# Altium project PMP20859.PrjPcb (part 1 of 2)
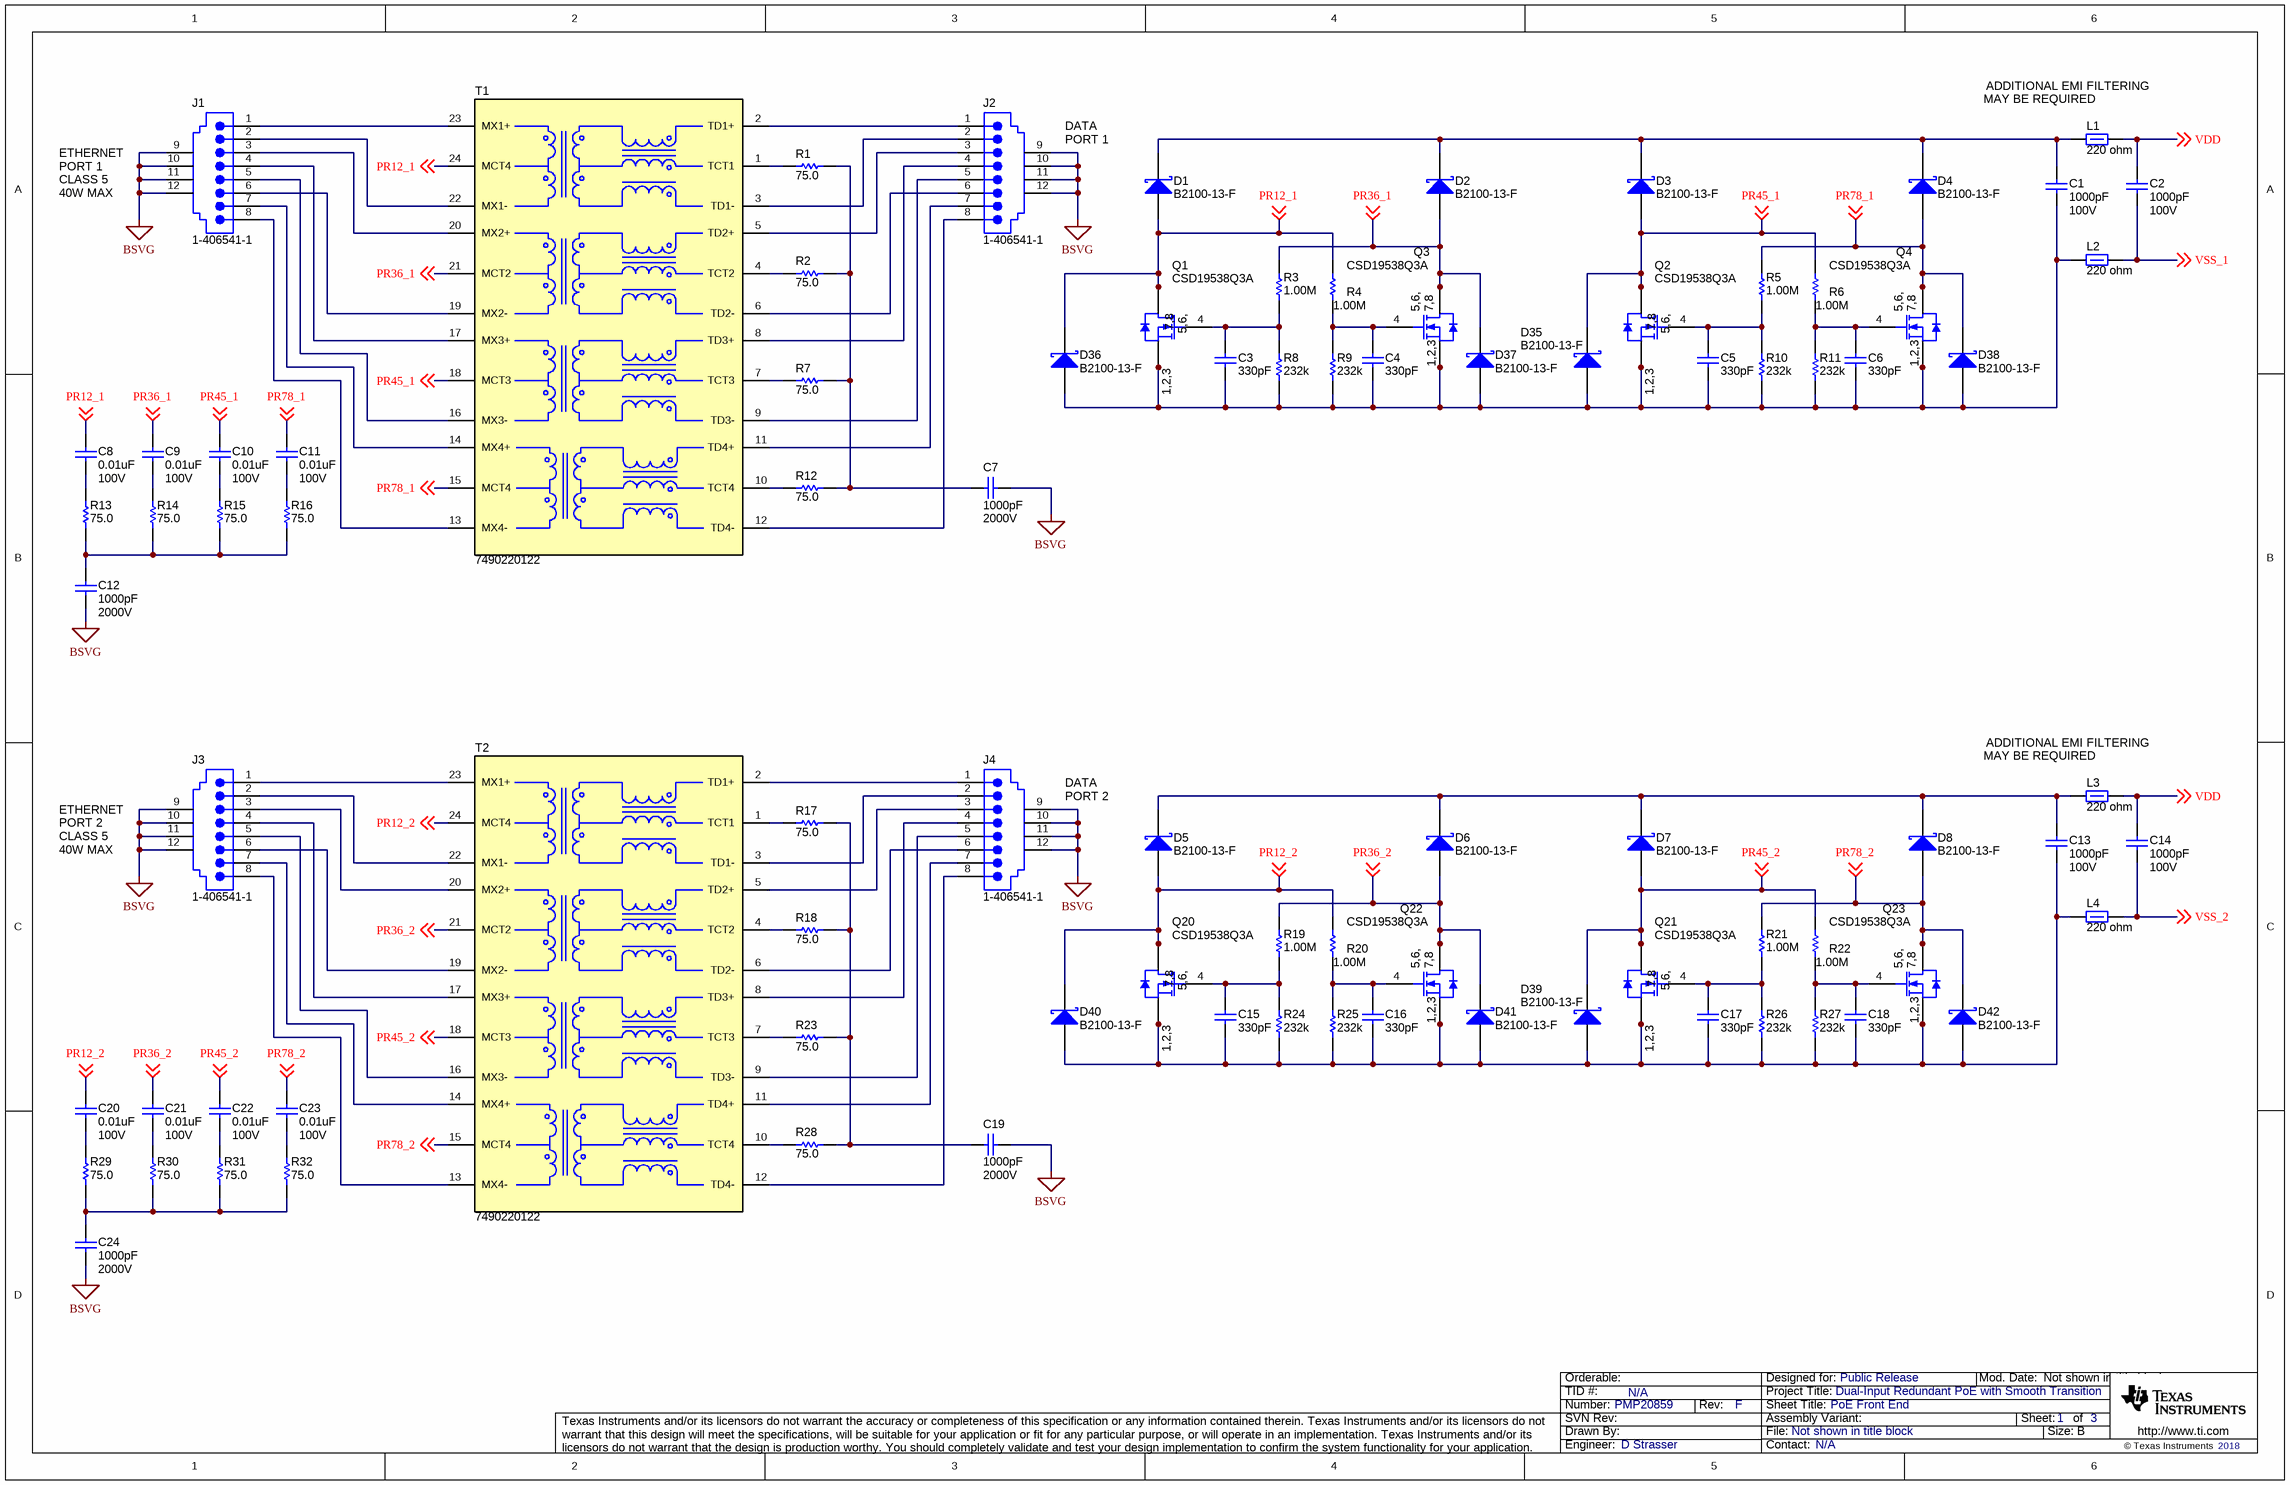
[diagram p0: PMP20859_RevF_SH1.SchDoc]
CopyrightYear: 2018; PCB_Layout: D Strasser; PCB_Rev: F; PRJ_Customer: Public Release; PRJ_Engineer: D Strasser; PRJ_Number: PMP20859; PRJ_Title: Dual-Input Redundant PoE with Smooth Transition; SCH_Rev: F; TechSupport: N/A; TID: N/A
3 sheets, 264 parts. Net scope: global (net labels, ports and power ports of the same name join across sheets).
Board file: PMP20859_RevF.PcbDoc
Sheets:
  PMP20859_RevF_SH1.SchDoc
  PMP20859_RevF_SH2.SchDoc
  PMP20859_RevF_SH3.SchDoc

## Sheet PMP20859_RevF_SH1.SchDoc: PoE Front End
size 431 x 279 mm; Date: Not shown in title block; ApprovedBy: Not shown in title block; CheckedBy: Not shown in title block; Author: Not shown in title block; CompanyName: Not shown in title block; Engineer: Not shown in title block; Organization: Not shown in title block; Address1: Not shown in title block; Address2: Not shown in title block; Address3: Not shown in title block; Address4: Not shown in title block; DocumentNumber: 1; Revision: Use project parameter SCH_Rev; SheetNumber: 1; SheetTotal: 3; PageSetup: Record=PageOptions¦CenterHorizontal=True¦CenterVertical=True¦PrintScale=1.00¦XCorrection=1.00¦YCorrection=1.00¦PrintKind=0¦BorderSize=5000000¦LeftOffset=0¦BottomOffset=0¦Orientation=2¦PaperLength=1000¦PaperWidth=1000¦Scale=100¦PaperSource=15¦PrintQuality=600¦MediaType=1¦DitherType=10¦PaperKind=Letter¦PrintScaleMode=1

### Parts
C1  ValueDisplayed: 1000pF  Value2: 100V  [0603_HV]  (hidden comment: Capacitor)
C2  ValueDisplayed: 1000pF  Value2: 100V  [0603_HV]  (hidden comment: Capacitor)
C3  ValueDisplayed: 330pF  [0603L]  (hidden comment: Capacitor)
C4  ValueDisplayed: 330pF  [0603L]  (hidden comment: Capacitor)
C5  ValueDisplayed: 330pF  [0603L]  (hidden comment: Capacitor)
C6  ValueDisplayed: 330pF  [0603L]  (hidden comment: Capacitor)
C7  ValueDisplayed: 1000pF  Value2: 2000V  [1812]  (hidden comment: Capacitor)
C8  ValueDisplayed: 0.01uF  Value2: 100V  [0603L]  (hidden comment: Capacitor)
C9  ValueDisplayed: 0.01uF  Value2: 100V  [0603L]  (hidden comment: Capacitor)
C10  ValueDisplayed: 0.01uF  Value2: 100V  [0603L]  (hidden comment: Capacitor)
C11  ValueDisplayed: 0.01uF  Value2: 100V  [0603L]  (hidden comment: Capacitor)
C12  ValueDisplayed: 1000pF  Value2: 2000V  [1812]  (hidden comment: Capacitor)
C13  ValueDisplayed: 1000pF  Value2: 100V  [0603_HV]  (hidden comment: Capacitor)
C14  ValueDisplayed: 1000pF  Value2: 100V  [0603_HV]  (hidden comment: Capacitor)
C15  ValueDisplayed: 330pF  [0603L]  (hidden comment: Capacitor)
C16  ValueDisplayed: 330pF  [0603L]  (hidden comment: Capacitor)
C17  ValueDisplayed: 330pF  [0603L]  (hidden comment: Capacitor)
C18  ValueDisplayed: 330pF  [0603L]  (hidden comment: Capacitor)
C19  ValueDisplayed: 1000pF  Value2: 2000V  [1812]  (hidden comment: Capacitor)
C20  ValueDisplayed: 0.01uF  Value2: 100V  [0603L]  (hidden comment: Capacitor)
C21  ValueDisplayed: 0.01uF  Value2: 100V  [0603L]  (hidden comment: Capacitor)
C22  ValueDisplayed: 0.01uF  Value2: 100V  [0603L]  (hidden comment: Capacitor)
C23  ValueDisplayed: 0.01uF  Value2: 100V  [0603L]  (hidden comment: Capacitor)
C24  ValueDisplayed: 1000pF  Value2: 2000V  [1812]  (hidden comment: Capacitor)
D1  B2100-13-F  [SMB]
D2  B2100-13-F  [SMB]
D3  B2100-13-F  [SMB]
D4  B2100-13-F  [SMB]
D5  B2100-13-F  [SMB]
D6  B2100-13-F  [SMB]
D7  B2100-13-F  [SMB]
D8  B2100-13-F  [SMB]
D35  B2100-13-F  [SMB]
D36  B2100-13-F  [SMB]
D37  B2100-13-F  [SMB]
D38  B2100-13-F  [SMB]
D39  B2100-13-F  [SMB]
D40  B2100-13-F  [SMB]
D41  B2100-13-F  [SMB]
D42  B2100-13-F  [SMB]
J1  1-406541-1  [TEC_1-406541-1]
J2  1-406541-1  [TEC_1-406541-1]
J3  1-406541-1  [TEC_1-406541-1]
J4  1-406541-1  [TEC_1-406541-1]
L1  value 220 ohm  [0603]  (hidden comment: Ferrite_Bead)
L2  value 220 ohm  [0603]  (hidden comment: Ferrite_Bead)
L3  value 220 ohm  [0603]  (hidden comment: Ferrite_Bead)
L4  value 220 ohm  [0603]  (hidden comment: Ferrite_Bead)
Q1  CSD19538Q3A  [DNH0008A_NV]
Q2  CSD19538Q3A  [DNH0008A_NV]
Q3  CSD19538Q3A  [DNH0008A_NV]
Q4  CSD19538Q3A  [DNH0008A_NV]
Q20  CSD19538Q3A  [DNH0008A_NV]
Q21  CSD19538Q3A  [DNH0008A_NV]
Q22  CSD19538Q3A  [DNH0008A_NV]
Q23  CSD19538Q3A  [DNH0008A_NV]
R1  value 75.0  [0603L]  (hidden comment: Resistor)
R2  value 75.0  [0603L]  (hidden comment: Resistor)
R3  ValueDisplayed: 1.00M  [0603L]  (hidden comment: Resistor)
R4  ValueDisplayed: 1.00M  [0603L]  (hidden comment: Resistor)
R5  ValueDisplayed: 1.00M  [0603L]  (hidden comment: Resistor)
R6  ValueDisplayed: 1.00M  [0603L]  (hidden comment: Resistor)
R7  value 75.0  [0603L]  (hidden comment: Resistor)
R8  ValueDisplayed: 232k  [0603L]  (hidden comment: Resistor)
R9  ValueDisplayed: 232k  [0603L]  (hidden comment: Resistor)
R10  ValueDisplayed: 232k  [0603L]  (hidden comment: Resistor)
R11  ValueDisplayed: 232k  [0603L]  (hidden comment: Resistor)
R12  value 75.0  [0603L]  (hidden comment: Resistor)
R13  value 75.0  [0603L]  (hidden comment: Resistor)
R14  value 75.0  [0603L]  (hidden comment: Resistor)
R15  value 75.0  [0603L]  (hidden comment: Resistor)
R16  value 75.0  [0603L]  (hidden comment: Resistor)
R17  value 75.0  [0603L]  (hidden comment: Resistor)
R18  value 75.0  [0603L]  (hidden comment: Resistor)
R19  ValueDisplayed: 1.00M  [0603L]  (hidden comment: Resistor)
R20  ValueDisplayed: 1.00M  [0603L]  (hidden comment: Resistor)
R21  ValueDisplayed: 1.00M  [0603L]  (hidden comment: Resistor)
R22  ValueDisplayed: 1.00M  [0603L]  (hidden comment: Resistor)
R23  value 75.0  [0603L]  (hidden comment: Resistor)
R24  ValueDisplayed: 232k  [0603L]  (hidden comment: Resistor)
R25  ValueDisplayed: 232k  [0603L]  (hidden comment: Resistor)
R26  ValueDisplayed: 232k  [0603L]  (hidden comment: Resistor)
R27  ValueDisplayed: 232k  [0603L]  (hidden comment: Resistor)
R28  value 75.0  [0603L]  (hidden comment: Resistor)
R29  value 75.0  [0603L]  (hidden comment: Resistor)
R30  value 75.0  [0603L]  (hidden comment: Resistor)
R31  value 75.0  [0603L]  (hidden comment: Resistor)
R32  value 75.0  [0603L]  (hidden comment: Resistor)
T1  7490220122  [Wurth_7490220122]
T2  7490220122  [Wurth_7490220122]

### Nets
BSVG: C7.1 C12.2 C19.1 C24.2 J1.9 J1.10 J1.11 J1.12 J2.9 J2.10 J2.11 J2.12 J3.9 J3.10 J3.11 J3.12 J4.9 J4.10 J4.11 J4.12
PR12_1: C8.1 D1.2(A) D36.1(K) Q1.5(D) Q1.6(D) Q1.7(D) Q1.8(D) Q1.9(D) R4.1 T1.24(MCT4) ; off-sheet PR12_1
PR12_2: C20.1 D5.2(A) D40.1(K) Q20.5(D) Q20.6(D) Q20.7(D) Q20.8(D) Q20.9(D) R20.1 T2.24(MCT4) ; off-sheet PR12_2
PR36_1: C9.1 D2.2(A) D37.1(K) Q3.5(D) Q3.6(D) Q3.7(D) Q3.8(D) Q3.9(D) R3.1 T1.21(MCT2) ; off-sheet PR36_1
PR36_2: C21.1 D6.2(A) D41.1(K) Q22.5(D) Q22.6(D) Q22.7(D) Q22.8(D) Q22.9(D) R19.1 T2.21(MCT2) ; off-sheet PR36_2
PR45_1: C10.1 D3.2(A) D35.1(K) Q2.5(D) Q2.6(D) Q2.7(D) Q2.8(D) Q2.9(D) R6.1 T1.18(MCT3) ; off-sheet PR45_1
PR45_2: C22.1 D7.2(A) D39.1(K) Q21.5(D) Q21.6(D) Q21.7(D) Q21.8(D) Q21.9(D) R22.1 T2.18(MCT3) ; off-sheet PR45_2
PR78_1: C11.1 D4.2(A) D38.1(K) Q4.5(D) Q4.6(D) Q4.7(D) Q4.8(D) Q4.9(D) R5.1 T1.15(MCT4) ; off-sheet PR78_1
PR78_2: C23.1 D8.2(A) D42.1(K) Q23.5(D) Q23.6(D) Q23.7(D) Q23.8(D) Q23.9(D) R21.1 T2.15(MCT4) ; off-sheet PR78_2
VDD: C2.1 C14.1 L1.2 L3.2 ; off-sheet VDD
VSS_1: C2.2 L2.2 ; off-sheet VSS_1
VSS_2: C14.2 L4.2 ; off-sheet VSS_2
NetC1_1: C1.1 D1.1(K) D2.1(K) D3.1(K) D4.1(K) L1.1
NetC1_2: C1.2 C3.2 C4.2 C5.2 C6.2 D35.2(A) D36.2(A) D37.2(A) D38.2(A) L2.1 Q1.1(S) Q1.2(S) Q1.3(S) Q2.1(S) Q2.2(S) Q2.3(S) Q3.1(S) Q3.2(S) Q3.3(S) Q4.1(S) Q4.2(S) Q4.3(S) R8.1 R9.1 R10.1 R11.1
NetC3_1: C3.1 Q1.4(G) R3.2 R8.2
NetC4_1: C4.1 Q3.4(G) R4.2 R9.2
NetC5_1: C5.1 Q2.4(G) R5.2 R10.2
NetC6_1: C6.1 Q4.4(G) R6.2 R11.2
NetC7_2: C7.2 R1.1 R2.1 R7.1 R12.1
NetC8_2: C8.2 R13.2
NetC9_2: C9.2 R14.2
NetC10_2: C10.2 R15.2
NetC11_2: C11.2 R16.2
NetC12_1: C12.1 R13.1 R14.1 R15.1 R16.1
NetC13_1: C13.1 D5.1(K) D6.1(K) D7.1(K) D8.1(K) L3.1
NetC13_2: C13.2 C15.2 C16.2 C17.2 C18.2 D39.2(A) D40.2(A) D41.2(A) D42.2(A) L4.1 Q20.1(S) Q20.2(S) Q20.3(S) Q21.1(S) Q21.2(S) Q21.3(S) Q22.1(S) Q22.2(S) Q22.3(S) Q23.1(S) Q23.2(S) Q23.3(S) R24.1 R25.1 R26.1 R27.1
NetC15_1: C15.1 Q20.4(G) R19.2 R24.2
NetC16_1: C16.1 Q22.4(G) R20.2 R25.2
NetC17_1: C17.1 Q21.4(G) R21.2 R26.2
NetC18_1: C18.1 Q23.4(G) R22.2 R27.2
NetC19_2: C19.2 R17.1 R18.1 R23.1 R28.1
NetC20_2: C20.2 R29.2
NetC21_2: C21.2 R30.2
NetC22_2: C22.2 R31.2
NetC23_2: C23.2 R32.2
NetC24_1: C24.1 R29.1 R30.1 R31.1 R32.1
NetJ1_1: J1.1 T1.23(MX1+)
NetJ1_2: J1.2 T1.22(MX1-)
NetJ1_3: J1.3 T1.20(MX2+)
NetJ1_4: J1.4 T1.17(MX3+)
NetJ1_5: J1.5 T1.16(MX3-)
NetJ1_6: J1.6 T1.19(MX2-)
NetJ1_7: J1.7 T1.14(MX4+)
NetJ1_8: J1.8 T1.13(MX4-)
NetJ2_1: J2.1 T1.2(TD1+)
NetJ2_2: J2.2 T1.3(TD1-)
NetJ2_3: J2.3 T1.5(TD2+)
NetJ2_4: J2.4 T1.8(TD3+)
NetJ2_5: J2.5 T1.9(TD3-)
NetJ2_6: J2.6 T1.6(TD2-)
NetJ2_7: J2.7 T1.11(TD4+)
NetJ2_8: J2.8 T1.12(TD4-)
NetJ3_1: J3.1 T2.23(MX1+)
NetJ3_2: J3.2 T2.22(MX1-)
NetJ3_3: J3.3 T2.20(MX2+)
NetJ3_4: J3.4 T2.17(MX3+)
NetJ3_5: J3.5 T2.16(MX3-)
NetJ3_6: J3.6 T2.19(MX2-)
NetJ3_7: J3.7 T2.14(MX4+)
NetJ3_8: J3.8 T2.13(MX4-)
NetJ4_1: J4.1 T2.2(TD1+)
NetJ4_2: J4.2 T2.3(TD1-)
NetJ4_3: J4.3 T2.5(TD2+)
NetJ4_4: J4.4 T2.8(TD3+)
NetJ4_5: J4.5 T2.9(TD3-)
NetJ4_6: J4.6 T2.6(TD2-)
NetJ4_7: J4.7 T2.11(TD4+)
NetJ4_8: J4.8 T2.12(TD4-)
NetR1_2: R1.2 T1.1(TCT1)
NetR2_2: R2.2 T1.4(TCT2)
NetR7_2: R7.2 T1.7(TCT3)
NetR12_2: R12.2 T1.10(TCT4)
NetR17_2: R17.2 T2.1(TCT1)
NetR18_2: R18.2 T2.4(TCT2)
NetR23_2: R23.2 T2.7(TCT3)
NetR28_2: R28.2 T2.10(TCT4)

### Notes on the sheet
- (near L1) MAY BE REQUIRED
- (near L1) ADDITIONAL EMI FILTERING
- ETHERNET
- PORT 1
- (near J2) DATA
- (near J2) PORT 1
- 40W MAX
- CLASS 5
- (near L3) MAY BE REQUIRED
- (near L3) ADDITIONAL EMI FILTERING
- PORT 2
- (near J4) DATA
- (near J4) PORT 2

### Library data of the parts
C1 C2 C13 C14 = CMP-0007053-4: CAP, CERM, 1000 pF, 100 V, +/- 10%, X7R, 0603; PartNumber: C1608X7R2A102K080AA; Manufacturer: TDK; Polarized: N; Value: 1000pF; U/M: EA; Cap_F: 1nF; Value1: Unknown; TaMin_C: -55°C; TaMax_C: 125°C; Cap_Case: 0603; SizeArea_mm2: 1.28; SizeAreaWB_mm2: 4.68; SizeX_mm: 1.6; SizeY_mm: 0.8; SizeZ_mm: 1; AEC Category: Q200
C3-C6 C15-C18 = CMP-0007209-4: CAP, CERM, 330 pF, 50 V, +/- 5%, C0G/NP0, 0603; PartNumber: GRM1885C1H331JA01D; Manufacturer: MuRata; Polarized: N; Value: 330pF; U/M: EA; Value1: Unknown; VDC_V: 50V; TaMin_C: -55°C; TaMax_C: 125°C; Cap_Case: 0603; SizeArea_mm2: 1.28; SizeAreaWB_mm2: 4.68; SizeX_mm: 1.6; SizeY_mm: 0.8; SizeZ_mm: 1; AEC Category: Q200
C7 C12 C19 C24 = CMP-0009438-2: CAP, CERM, 1000 pF, 2000 V, +/- 10%, X7R, 1812; PartNumber: GR443QR73D102KW01L; Manufacturer: MuRata; Polarized: N; Value: 1000pF; U/M: EA; Cap_F: 1nF; Value1: Unknown; VDC_V: 2kV; TaMin_C: -55°C; TaMax_C: 125°C; SizeArea_mm2: 14.4; SizeAreaWB_mm2: 23.1; SizeX_mm: 4.5; SizeY_mm: 3.2; SizeZ_mm: 1.35; AEC Category: Q200
C8-C11 C20-C23 = CMP-0007468-5: CAP, CERM, 0.01 uF, 100 V, +/- 10%, X7R, 0603; PartNumber: GRM188R72A103KA01D; Manufacturer: MuRata; Polarized: N; Value: 0.01uF; U/M: EA; Cap_F: 10nF; Value1: Unknown; TaMin_C: -55°C; TaMax_C: 125°C; Cap_Case: 0603; SizeArea_mm2: 1.28; SizeAreaWB_mm2: 4.68; SizeX_mm: 1.6; SizeY_mm: 0.8; SizeZ_mm: 1; AEC Category: Q200
D1-D8 D35-D42 = CMP-0028397-1: Diode, Schottky, 100 V, 2 A, SMB; Manufacturer: Diodes Inc.; Value: 100V; U/M: EA; Vf_V: 7.9dV; Value1: 2A; Value2: 0.79V; TJmax_C: 150°C; RJC_CperW: 15; AEC Category: Q101; Green_Lifecycle: Active; Green_REACh: Passed; SizeArea_mm2: 21.336; SizeAreaWB_mm2: 44.156; SizeX_mm: 5.6; SizeY_mm: 3.81; SizeZ_mm: 2.6
J1-J4 = CMP-0054918-1: RJ45, No LED, tab up, R/A, TH; Manufacturer: TE Connectivity; CNHeader: FALSE; ContactFinish: Gold; CT: TRUE; Green_Lifecycle: Active; Green_REACh: Passed
L1-L4 = CMP-0003425-2: Ferrite Bead, 220 ohm @ 100 MHz, 2.2 A, 0603; PartNumber: MPZ1608S221A; Manufacturer: TDK; Imax_A: 2.2A; DCR_ohm: 0.05; Value1: 0.05 ohm; ZTyp@100MHz_Ohm: 220; SizeArea_mm2: 1.28; SizeAreaWB_mm2: 4.68; SizeX_mm: 1.6; SizeY_mm: 0.8; SizeZ_mm: 1
Q1-Q4 Q20-Q23 = CMP-0000969-2: MOSFET, N-CH, 100 V, 5 A, DNH0008A (VSONP-8); Manufacturer: Texas Instruments; Alternate Manufacturer: None; U/M: EA; ChType: N; Value: 100V; Value2: 7.2 nC; QgTyp_nC: 7.2; Vgs_V: 20V; IdsMax_A: 5A; SizeAreaWB_mm2: 18.49; SizeArea_mm2: 10.89; SizeX_mm: 3.3; SizeZ_mm: 0.9; AEC Category: Q101
R1 R2 R7 R12-R18 R23 R28-R32 = CMP-0022590-4: RES, 75.0, 1%, 0.1 W, AEC-Q200 Grade 0, 0603; PartNumber: CRCW060375R0FKEA; Manufacturer: Vishay-Dale; Res_ohm: 75; Value_Code: 75R0; Power_W: 100mW; Value2: 0.1W; VDC_V: 75V; TempCo: 100 ppm/C; EIA_Code: E96; AEC Category: Q200; AEC Grade: 0; AEC Qualified: Y; SizeArea_mm2: 1.28; SizeX_mm: 1.6; SizeY_mm: 0.8; SizeZ_mm: 1
R3-R6 R19-R22 = CMP-0022138-4: RES, 1.00 M, 1%, 0.1 W, AEC-Q200 Grade 0, 0603; PartNumber: CRCW06031M00FKEA; Manufacturer: Vishay-Dale; Value: 1.00Meg; Res_ohm: 1M; Value_Code: 1M00; Power_W: 100mW; Value2: 0.1W; VDC_V: 75V; TempCo: 100 ppm/C; EIA_Code: E96; SizeArea_mm2: 1.28; SizeX_mm: 1.6; SizeY_mm: 0.8; SizeZ_mm: 1; AEC Category: Q200; AEC Qualified: Y; AEC Grade: 0
R8-R11 R24-R27 = CMP-0022224-4: RES, 232 k, 1%, 0.1 W, AEC-Q200 Grade 0, 0603; PartNumber: CRCW0603232KFKEA; Manufacturer: Vishay-Dale; Value: 232k; Power_W: 100mW; Value2: 0.1W; VDC_V: 75V; TempCo: 100 ppm/C; EIA_Code: E96; SizeArea_mm2: 1.28; SizeX_mm: 1.6; SizeY_mm: 0.8; SizeZ_mm: 1; AEC Category: Q200; AEC Qualified: Y; AEC Grade: 0
T1 T2 = CMP-0030597-1: Transformer, 350 uH, SMT; Manufacturer: Wurth Elektronik; Value: 350uH; Lp: 350; Ind_H: 350µH

## Sheet PMP20859_RevF_SH2.SchDoc: PoE PD's and Seamless Switching
size 431 x 279 mm; Date: Not shown in title block; ApprovedBy: Not shown in title block; CheckedBy: Not shown in title block; Author: Not shown in title block; CompanyName: Not shown in title block; Engineer: Not shown in title block; Organization: Not shown in title block; Address1: Not shown in title block; Address2: Not shown in title block; Address3: Not shown in title block; Address4: Not shown in title block; DocumentNumber: 2; Revision: Use project parameter SCH_Rev; SheetNumber: 2; SheetTotal: 3; PageSetup: Record=PageOptions¦CenterHorizontal=True¦CenterVertical=True¦PrintScale=1.00¦XCorrection=1.00¦YCorrection=1.00¦PrintKind=0¦BorderSize=5000000¦LeftOffset=0¦BottomOffset=0¦Orientation=2¦PaperLength=1000¦PaperWidth=1000¦Scale=100¦PaperSource=15¦PrintQuality=600¦MediaType=1¦DitherType=10¦PaperKind=Letter¦PrintScaleMode=1
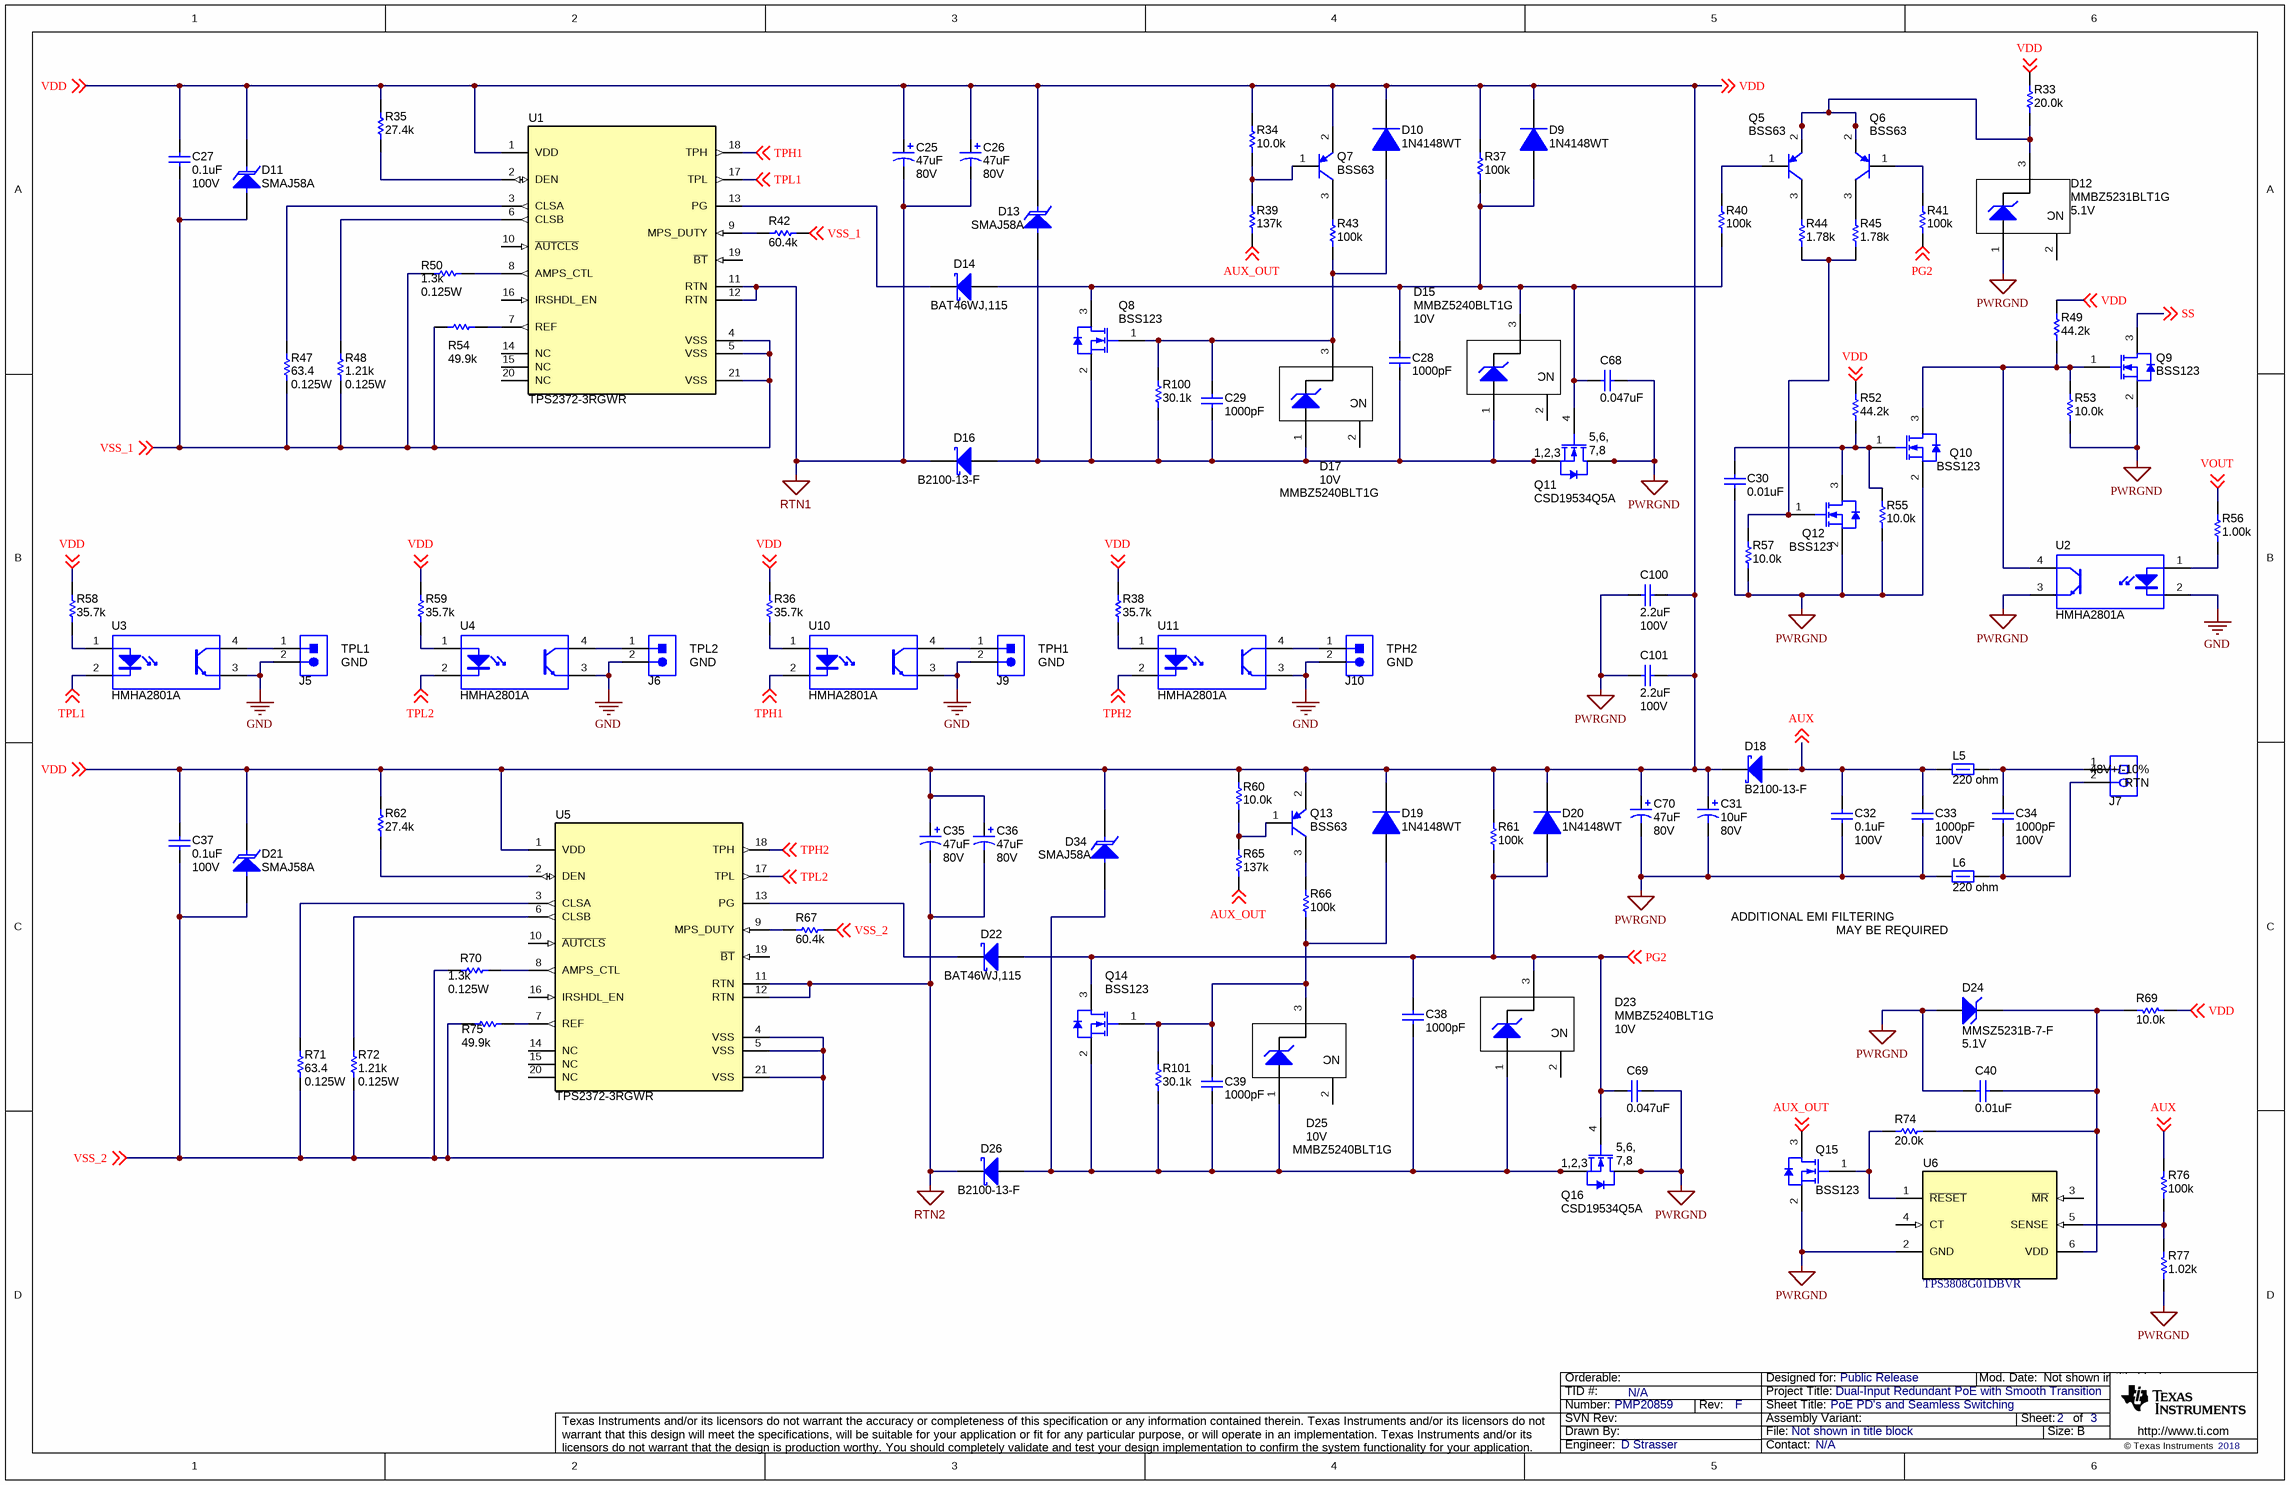
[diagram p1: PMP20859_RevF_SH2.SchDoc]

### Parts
C25  ValueDisplayed: 47uF  Value2: 80V  [SM_RADIAL_G]  (hidden comment: Cap_Polarized)
C26  ValueDisplayed: 47uF  Value2: 80V  [SM_RADIAL_G]  (hidden comment: Cap_Polarized)
C27  ValueDisplayed: 0.1uF  Value2: 100V  [0805_HV]  (hidden comment: Capacitor)
C28  ValueDisplayed: 1000pF  [0603]  (hidden comment: Capacitor)
C29  ValueDisplayed: 1000pF  [0603]  (hidden comment: Capacitor)
C30  ValueDisplayed: 0.01uF  [0603L]  (hidden comment: Capacitor)
C31  ValueDisplayed: 10uF  Value2: 80V  [SM_RADIAL_E]  (hidden comment: Cap_Polarized)
C32  ValueDisplayed: 0.1uF  Value2: 100V  [0805_HV]  (hidden comment: Capacitor)
C33  ValueDisplayed: 1000pF  Value2: 100V  [0603_HV]  (hidden comment: Capacitor)
C34  ValueDisplayed: 1000pF  Value2: 100V  [0603_HV]  (hidden comment: Capacitor)
C35  ValueDisplayed: 47uF  Value2: 80V  [SM_RADIAL_G]  (hidden comment: Cap_Polarized)
C36  ValueDisplayed: 47uF  Value2: 80V  [SM_RADIAL_G]  (hidden comment: Cap_Polarized)
C37  ValueDisplayed: 0.1uF  Value2: 100V  [0805_HV]  (hidden comment: Capacitor)
C38  ValueDisplayed: 1000pF  [0603]  (hidden comment: Capacitor)
C39  ValueDisplayed: 1000pF  [0603]  (hidden comment: Capacitor)
C40  ValueDisplayed: 0.01uF  [0603L]  (hidden comment: Capacitor)
C68  ValueDisplayed: 0.047uF  [0805_HV]  (hidden comment: Capacitor)
C69  ValueDisplayed: 0.047uF  [0805_HV]  (hidden comment: Capacitor)
C70  ValueDisplayed: 47uF  Value2: 80V  [SM_RADIAL_G]  (hidden comment: Cap_Polarized)
C100  ValueDisplayed: 2.2uF  Value2: 100V  [1210_270]  (hidden comment: Capacitor)
C101  ValueDisplayed: 2.2uF  Value2: 100V  [1210_270]  (hidden comment: Capacitor)
D9  1N4148WT  [Fairchild_SOD-523F]
D10  1N4148WT  [Fairchild_SOD-523F]
D11  SMAJ58A  [SMA]
D12  MMBZ5231BLT1G  value 5.1V  [SOT-23]
D13  SMAJ58A  [SMA]
D14  BAT46WJ,115  [SOD-323F]
D15  MMBZ5240BLT1G  value 10V  [SOT-23]
D16  B2100-13-F  [SMB]
D17  MMBZ5240BLT1G  value 10V  [SOT-23]
D18  B2100-13-F  [SMB]
D19  1N4148WT  [Fairchild_SOD-523F]
D20  1N4148WT  [Fairchild_SOD-523F]
D21  SMAJ58A  [SMA]
D22  BAT46WJ,115  [SOD-323F]
D23  MMBZ5240BLT1G  value 10V  [SOT-23]
D24  MMSZ5231B-7-F  value 5.1V  [SOD-123]
D25  MMBZ5240BLT1G  value 10V  [SOT-23]
D26  B2100-13-F  [SMB]
D34  SMAJ58A  [SMA]
J5  PEC02SAAN  [CONN_PEC02SAAN]  (value not drawn)
J6  PEC02SAAN  [CONN_PEC02SAAN]  (value not drawn)
J7  ED555/2DS  [TERM_BLK_ED555-2DS]  (value not drawn)
J9  PEC02SAAN  [CONN_PEC02SAAN]  (value not drawn)
J10  PEC02SAAN  [CONN_PEC02SAAN]  (value not drawn)
L5  value 220 ohm  [0603]  (hidden comment: Ferrite_Bead)
L6  value 220 ohm  [0603]  (hidden comment: Ferrite_Bead)
Q5  BSS63  [SOT-23]
Q6  BSS63  [SOT-23]
Q7  BSS63  [SOT-23]
Q8  BSS123  [SOT-23]
Q9  BSS123  [SOT-23]
Q10  BSS123  [SOT-23]
Q11  CSD19534Q5A  [DQJ0008A]
Q12  BSS123  [SOT-23]
Q13  BSS63  [SOT-23]
Q14  BSS123  [SOT-23]
Q15  BSS123  [SOT-23]
Q16  CSD19534Q5A  [DQJ0008A]
R33  ValueDisplayed: 20.0k  [0603]  (hidden comment: Resistor)
R34  ValueDisplayed: 10.0k  [0603]  (hidden comment: Resistor)
R35  ValueDisplayed: 27.4k  [0603]  (hidden comment: Resistor)
R36  Res_ohm: 35.7k  [0603]  (hidden comment: RC0603FR-0735K7L)
R37  ValueDisplayed: 100k  [0603]  (hidden comment: Resistor)
R38  Res_ohm: 35.7k  [0603]  (hidden comment: RC0603FR-0735K7L)
R39  ValueDisplayed: 137k  [0603]  (hidden comment: Resistor)
R40  ValueDisplayed: 100k  [0603]  (hidden comment: Resistor)
R41  ValueDisplayed: 100k  [0603]  (hidden comment: Resistor)
R42  Res_ohm: 60.4k  [0603]  (hidden comment: CRCW060360K4FKEA)
R43  ValueDisplayed: 100k  [0603]  (hidden comment: Resistor)
R44  ValueDisplayed: 1.78k  [0603]  (hidden comment: Resistor)
R45  ValueDisplayed: 1.78k  [0603]  (hidden comment: Resistor)
R47  ValueDisplayed: 63.4  Value2: 0.125W  [0805_HV]  (hidden comment: Resistor)
R48  ValueDisplayed: 1.21k  Value2: 0.125W  [0805_HV]  (hidden comment: CRCW08051K21FKEA)
R49  ValueDisplayed: 44.2k  [0603L]  (hidden comment: Resistor)
R50  Value2: 0.125W  ValueDisplayed: 1.3k  [0805_HV]  (hidden comment: Resistor)
R52  ValueDisplayed: 44.2k  [0603L]  (hidden comment: Resistor)
R53  ValueDisplayed: 10.0k  [0603L]  (hidden comment: Resistor)
R54  ValueDisplayed: 49.9k  [0603L]  (hidden comment: Resistor)
R55  ValueDisplayed: 10.0k  [0603L]  (hidden comment: Resistor)
R56  ValueDisplayed: 1.00k  [0603L]  (hidden comment: Resistor)
R57  ValueDisplayed: 10.0k  [0603L]  (hidden comment: Resistor)
R58  Res_ohm: 35.7k  [0603]  (hidden comment: RC0603FR-0735K7L)
R59  Res_ohm: 35.7k  [0603]  (hidden comment: RC0603FR-0735K7L)
R60  ValueDisplayed: 10.0k  [0603]  (hidden comment: CRCW060310K0FKEA)
R61  ValueDisplayed: 100k  [0603]  (hidden comment: Resistor)
R62  ValueDisplayed: 27.4k  [0603]  (hidden comment: Resistor)
R65  ValueDisplayed: 137k  [0603]  (hidden comment: Resistor)
R66  ValueDisplayed: 100k  [0603]  (hidden comment: Resistor)
R67  ValueDisplayed: 60.4k  [0603]  (hidden comment: CRCW060360K4FKEA)
R69  ValueDisplayed: 10.0k  [0603L]  (hidden comment: Resistor)
R70  Value2: 0.125W  ValueDisplayed: 1.3k  [0805_HV]  (hidden comment: Resistor)
R71  ValueDisplayed: 63.4  Value2: 0.125W  [0805_HV]  (hidden comment: Resistor)
R72  ValueDisplayed: 1.21k  Value2: 0.125W  [0805_HV]  (hidden comment: CRCW08051K21FKEA)
R74  ValueDisplayed: 20.0k  [0603L]  (hidden comment: Resistor)
R75  ValueDisplayed: 49.9k  [0603L]  (hidden comment: Resistor)
R76  ValueDisplayed: 100k  [0603L]  (hidden comment: Resistor)
R77  ValueDisplayed: 1.02k  [0603]  (hidden comment: Resistor)
R100  ValueDisplayed: 30.1k  [0603]  (hidden comment: Resistor)
R101  ValueDisplayed: 30.1k  [0603]  (hidden comment: Resistor)
U1  TPS2372-3RGWR  [RGW0020B]
U2  HMHA2801A  [MFP04A]
U3  HMHA2801A  [MFP04A]
U4  HMHA2801A  [MFP04A]
U5  TPS2372-3RGWR  [RGW0020B]
U6  TPS3808G01DBVR  [DBV0006A_N]
U10  HMHA2801A  [MFP04A]
U11  HMHA2801A  [MFP04A]

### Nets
GND: J5.2 J6.2 J9.2 J10.2 U2.2(K) U3.3(E) U4.3(E) U10.3(E) U11.3(E)
PWRGND: C30.2 C31.2(-) C32.2 C33.2 C40.1 C68.1 C69.1 C70.2(-) C100.1 C101.1 D12.1(A) D24.2(A) L6.2 Q9.2(S) Q10.2(S) Q11.5(D) Q11.6(D) Q11.7(D) Q11.8(D) Q11.9(D) Q12.2(S) Q15.2(S) Q16.5(D) Q16.6(D) Q16.7(D) Q16.8(D) Q16.9(D) R53.1 R55.1 R57.1 R77.1 U2.3(E) U6.2(GND)
RTN1: C25.2(-) C26.2(-) D16.1(K) U1.11(RTN) U1.12(RTN)
RTN2: C35.2(-) C36.2(-) D26.1(K) U5.11(RTN) U5.12(RTN)
AUX: C32.1 C33.1 D18.2(A) L5.2 R76.2 ; off-sheet AUX
AUX_OUT: Q15.3(D) R39.2 R65.2 ; off-sheet AUX_OUT
PG2: C38.1 C69.2 D20.2(A) D22.2(A) D23.3(K) Q14.3(D) Q16.4(G) R41.1 R61.1 ; off-sheet PG2
SS: Q9.3(D) ; off-sheet SS
TPH1: U1.18(TPH) U10.2(K) ; off-sheet TPH1
TPH2: U5.18(TPH) U11.2(K) ; off-sheet TPH2
TPL1: U1.17(TPL) U3.2(K) ; off-sheet TPL1
TPL2: U4.2(K) U5.17(TPL) ; off-sheet TPL2
VDD: C25.1(+) C26.1(+) C27.2 C31.1(+) C35.1(+) C36.1(+) C37.2 C70.1(+) C100.2 C101.2 D9.1(K) D10.1(K) D11.1(K) D13.1(K) D18.1(K) D19.1(K) D20.1(K) D21.1(K) D34.1(K) Q7.2(E) Q13.2(E) R33.2 R34.2 R35.2 R36.1 R37.2 R38.1 R49.2 R52.1 R58.1 R59.1 R60.2 R61.2 R62.2 R69.2 U1.1(VDD) U5.1(VDD) ; off-sheet VDD
VOUT: R56.2 ; off-sheet VOUT
VSS_1: C27.1 D11.2(A) R42.2 R47.1 R48.1 R50.2 R54.1 U1.4(VSS) U1.5(VSS) U1.21(VSS) ; off-sheet VSS_1
VSS_2: C37.1 D21.2(A) R67.2 R70.2 R71.1 R72.1 R75.1 U5.4(VSS) U5.5(VSS) U5.21(VSS) ; off-sheet VSS_2
NetC28_1: C28.1 C68.2 D9.2(A) D14.2(A) D15.3(K) Q8.3(D) Q11.4(G) R37.1 R40.1
NetC28_2: C28.2 C29.2 D13.2(A) D15.1(A) D16.2(A) D17.1(A) Q8.2(S) Q11.1(S) Q11.2(S) Q11.3(S) R100.1
NetC29_1: C29.1 D10.2(A) D17.3(K) Q8.1(G) R43.1 R100.2
NetC30_1: C30.1 Q10.1(G) Q12.3(D) R52.2 R55.2
NetC34_1: C34.1 J7.1 L5.1
NetC34_2: C34.2 J7.2 L6.1
NetC38_2: C38.2 C39.2 D23.1(A) D25.1(A) D26.2(A) D34.2(A) Q14.2(S) Q16.1(S) Q16.2(S) Q16.3(S) R101.1
NetC39_1: C39.1 D19.2(A) D25.3(K) Q14.1(G) R66.1 R101.2
NetC40_2: C40.2 D24.1(K) R69.1 R74.1 U6.6(VDD)
NetD12_3: D12.3(K) Q5.2(E) Q6.2(E) R33.1
NetD14_1: D14.1(K) U1.13(PG)
NetD22_1: D22.1(K) U5.13(PG)
NetJ5_1: J5.1 U3.4(C)
NetJ6_1: J6.1 U4.4(C)
NetJ9_1: J9.1 U10.4(C)
NetJ10_1: J10.1 U11.4(C)
NetQ5_1: Q5.1(B) R40.2
NetQ5_3: Q5.3(C) R44.1
NetQ6_1: Q6.1(B) R41.2
NetQ6_3: Q6.3(C) R45.2
NetQ7_1: Q7.1(B) R34.1 R39.1
NetQ7_3: Q7.3(C) R43.2
NetQ9_1: Q9.1(G) Q10.3(D) R49.1 R53.2 U2.4(C)
NetQ12_1: Q12.1(G) R44.2 R45.1 R57.2
NetQ13_1: Q13.1(B) R60.1 R65.1
NetQ13_3: Q13.3(C) R66.2
NetQ15_1: Q15.1(G) R74.2 U6.1(~{RESET})
NetR35_1: R35.1 U1.2(DEN)
NetR36_2: R36.2 U10.1(A)
NetR38_2: R38.2 U11.1(A)
NetR42_1: R42.1 U1.9(MPS_DUTY)
NetR47_2: R47.2 U1.3(CLSA)
NetR48_2: R48.2 U1.6(CLSB)
NetR50_1: R50.1 U1.8(AMPS_CTL)
NetR54_2: R54.2 U1.7(REF)
NetR56_1: R56.1 U2.1(A)
NetR58_2: R58.2 U3.1(A)
NetR59_2: R59.2 U4.1(A)
NetR62_1: R62.1 U5.2(DEN)
NetR67_1: R67.1 U5.9(MPS_DUTY)
NetR70_1: R70.1 U5.8(AMPS_CTL)
NetR71_2: R71.2 U5.3(CLSA)
NetR72_2: R72.2 U5.6(CLSB)
NetR75_2: R75.2 U5.7(REF)
NetR76_1: R76.1 R77.2 U6.5(SENSE)

Not connected (* = marked no-connect by the designer): D12 2(NC); D15 2(NC); D17 2(NC); D23 2(NC); D25 2(NC); U1 10(~{AUTCLS}) 14(NC) 15(NC) 16(IRSHDL_EN) 19(~{BT}) 20(NC); U5 10(~{AUTCLS}) 14(NC) 15(NC) 16(IRSHDL_EN) 19(~{BT}) 20(NC); U6 3(~{MR}) 4(CT)

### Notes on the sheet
- TPL1
- (near J5) GND
- TPL2
- (near J6) GND
- TPH1
- (near J9) GND
- (near J10) TPH2
- (near J10) GND
- (near J7) 48V+/-10%
- (near J7) RTN
- (near L6) ADDITIONAL EMI FILTERING
- MAY BE REQUIRED

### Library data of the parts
C25 C26 C35 C36 C70 = CMP-0011200-2: CAP, AL, 47 uF, 80 V, +/- 20%, 0.7 ohm, AEC-Q200 Grade 2, SMD; PartNumber: EEE-FK1K470P; Manufacturer: Panasonic; Polarized: Y; CompType: Capacitor; Value: 47uF; U/M: EA; Cap_F: 47µF; Value1: 0.7 ohm; ESR_ohm: 7d; IRMS_A: 2dA; TaMin_C: -55°C; TaMax_C: 105°C; Cap_Case: G; AEC Category: Q200; AEC Grade: 2; SizeAreaWB_mm2: 172.2; SizeArea_mm2: 123.6; SizeX_mm: 12; SizeY_mm: 10.3; SizeZ_mm: 10.2
C27 C32 C37 = CMP-0007886-2: CAP, CERM, 0.1 uF, 100 V, +/- 10%, X7R, 0805; PartNumber: C2012X7R2A104K125AA; Manufacturer: TDK; Polarized: N; Value: 0.1uF; U/M: EA; Cap_F: 100nF; ESR_ohm: 0.020726; Value1: 0.020726 ohm; IRMS_A: 1.456A; TaMin_C: -55°C; TaMax_C: 125°C; Cap_Case: 0805; SizeArea_mm2: 2.5; SizeAreaWB_mm2: 6.75; SizeX_mm: 2; SizeY_mm: 1.25; SizeZ_mm: 1.45; AEC Category: Q200
C28 C29 C38 C39 = CMP-0007432-5: CAP, CERM, 1000 pF, 50 V, +/- 10%, X7R, 0603; PartNumber: GRM188R71H102KA01D; Manufacturer: MuRata; Polarized: N; Value: 1000pF; U/M: EA; Cap_F: 1nF; Value1: Unknown; VDC_V: 50V; TaMin_C: -55°C; TaMax_C: 125°C; SizeArea_mm2: 1.28; SizeAreaWB_mm2: 4.68; SizeX_mm: 1.6; SizeY_mm: 0.8; SizeZ_mm: 1; AEC Category: Q200
C30 C40 = CMP-0007043-4: CAP, CERM, 0.01 uF, 50 V, +/- 10%, X7R, 0603; PartNumber: C1608X7R1H103K080AA; Manufacturer: TDK; Polarized: N; Value: 0.01uF; U/M: EA; Cap_F: 10nF; ESR_ohm: 0.0539; Value1: 0.0539 ohm; VDC_V: 50V; TaMin_C: -55°C; TaMax_C: 125°C; Cap_Case: 0603; SizeArea_mm2: 1.28; SizeAreaWB_mm2: 4.68; SizeX_mm: 1.6; SizeY_mm: 0.8; SizeZ_mm: 1; AEC Category: Q200
C31 = CMP-0011195-2: CAP, AL, 10 uF, 80 V, +/- 20%, 2.4 ohm, AEC-Q200 Grade 2, SMD; PartNumber: EEE-FK1K100P; Manufacturer: Panasonic; Polarized: Y; CompType: Capacitor; Value: 10uF; U/M: EA; Cap_F: 10µF; Value1: 2.4 ohm; ESR_ohm: 2.4; IRMS_A: 60mA; TaMin_C: -55°C; TaMax_C: 105°C; Cap_Case: E; AEC Category: Q200; AEC Grade: 2; SizeAreaWB_mm2: 118.45; SizeArea_mm2: 78.85; SizeX_mm: 9.5; SizeY_mm: 8.3; SizeZ_mm: 6.2
C33 C34 = CMP-0007053-4: as C1 on sheet PMP20859_RevF_SH1
C68 C69 = CMP-0007887-2: CAP, CERM, 0.047 uF, 100 V, +/- 10%, X7R, 0805; PartNumber: C2012X7R2A473K125AA; Manufacturer: TDK; Polarized: N; U/M: EA; Cap_F: 47nF; ESR_ohm: 0.049089; Value1: 0.049089 ohm; VDC_V: 100V; IRMS_A: 9.63171dA; TaMin_C: -55°C; TaMax_C: 125°C; Cap_Case: 0805; SizeArea_mm2: 2.5; SizeAreaWB_mm2: 6.75; SizeX_mm: 2; SizeY_mm: 1.25; SizeZ_mm: 1.45; AEC Category: Q200
C100 C101 = CMP-0009232-2: CAP, CERM, 2.2 uF, 100 V, +/- 10%, X7R, 1210; PartNumber: GRM32ER72A225KA35L; Manufacturer: MuRata; Polarized: N; Value: 2.2uF; U/M: EA; Cap_F: 2.2µF; ESR_ohm: 7m; Value1: 0.007 ohm; IRMS_A: 4.4A; TaMin_C: -55°C; TaMax_C: 125°C; Cap_Case: 1210; SizeArea_mm2: 8; SizeAreaWB_mm2: 14.7; SizeX_mm: 3.2; SizeY_mm: 2.5; SizeZ_mm: 2.7; AEC Category: Q200
D9 D10 D19 D20 = CMP-0076982-1: Diode, Switching, 75 V, 0.3 A, SOD-523F; Manufacturer: Fairchild Semiconductor; U/M: EA; Value: 75V; Value1: 0.3A; Io_A: 3dA; TJmax_C: 150°C; SizeAreaWB_mm2: 4.68; SizeArea_mm2: 1.28; SizeX_mm: 1.6; SizeY_mm: 0.8; SizeZ_mm: 0.7; AEC Category: Q101; Green_Lifecycle: Not Set; Green_REACh: Incomplete
D11 D13 D21 D34 = CMP-0005485-2: Diode, TVS, Uni, 58 V, SMA; Manufacturer: Diodes Inc.; Value: 58V; U/M: EA; Power_W: 1W; AEC Category: Q101; SizeArea_mm2: 16.3228; SizeAreaWB_mm2: 37.3428; SizeX_mm: 5.59; SizeY_mm: 2.92; SizeZ_mm: 2.87
D12 = CMP-0005999-1: Diode, Zener, 5.1 V, 225 mW, SOT-23; Manufacturer: ON Semiconductor; U/M: EA; Power_W: 225mW; Value1: 0.225W; RJA_CperW: 556; SizeAreaWB_mm2: 14; SizeArea_mm2: 7.5; SizeX_mm: 2.5; SizeY_mm: 3; SizeZ_mm: 1.1; AEC Category: Q101
D14 D22 = CMP-0076946-1: Diode, Schottky, 100 V, 0.25 A, SOD-323F; Manufacturer: Nexperia; U/M: EA; Vf_V: 8.5dV; Value: 100V; Value1: 0.25A; Value2: 0.85V; Io_A: 2.5dA; TJmax_C: 150°C; AEC Category: Q101; Green_Lifecycle: Not Set; Green_REACh: Incomplete; SizeArea_mm2: 3.125; SizeAreaWB_mm2: 7.875; SizeX_mm: 2.5; SizeY_mm: 1.25; SizeZ_mm: 0.8
D15 D17 D23 D25 = CMP-0005949-1: Diode, Zener, 10 V, 225 mW, SOT-23; Manufacturer: ON Semiconductor; U/M: EA; Power_W: 225mW; Value1: 0.225W; RJA_CperW: 556; SizeAreaWB_mm2: 14; SizeArea_mm2: 7.5; SizeX_mm: 2.5; SizeY_mm: 3; SizeZ_mm: 1.1; AEC Category: Q101
D16 D18 D26 = CMP-0028397-1: Diode, Schottky, 100 V, 2 A, SMB; Manufacturer: Diodes Inc.; U/M: EA; Vf_V: 7.9dV; Value: 100V; Value1: 2A; Value2: 0.79V; TJmax_C: 150°C; RJC_CperW: 15; AEC Category: Q101; Green_Lifecycle: Active; Green_REACh: Passed; SizeArea_mm2: 21.336; SizeAreaWB_mm2: 44.156; SizeX_mm: 5.6; SizeY_mm: 3.81; SizeZ_mm: 2.6
D24 = CMP-0005802-1: Diode, Zener, 5.1 V, 500 mW, SOD-123; Manufacturer: Diodes Inc.; U/M: EA; Power_W: 500mW; Value1: 0.5W; RJA_CperW: 350; SizeAreaWB_mm2: 13.095; SizeArea_mm2: 6.545; SizeX_mm: 3.85; SizeY_mm: 1.7; SizeZ_mm: 1.35; AEC Category: Q101
J5 J6 J9 J10 = CMP-0002337-1: Header, 100mil, 2x1, Tin, TH; Manufacturer: Sullins Connector Solutions; Cert_UL: Y; CNHeader: TRUE; CT: FALSE; Current_A: 3A; Gender: Male; Green_Lifecycle: Not Set; Green_REACh: Incomplete; Pitch_mm: 2.54; Row_Count: 1; Shrouded: N; Voltage_V: 1.8kV
J7 = CMP-0074913-1: Terminal Block, 3.5mm Pitch, 2x1, TH; Manufacturer: On-Shore Technology; Cert_CULUS: Y; CNHeader: False; ContactFinish: Brass; CT: True; Current_A: 6A; Gender: Female; Green_Lifecycle: Active; Green_REACh: Passed; Pitch_mm: 3.5; Row_Count: 1; Shrouded: N; Voltage_V: 150V
L5 L6 = CMP-0003425-2: as L1 on sheet PMP20859_RevF_SH1
Q5-Q7 Q13 = CMP-0000366-2: Transistor, PNP, 100 V, 0.2 A, SOT-23; Manufacturer: Fairchild Semiconductor; CompType: BJT; PNP: 1; NPN: 0; Vceo_V: 100V; Vcesat1_V: 2.5dV; Value: 100 V; IcRated_A: 2dA; Value1: 0.2 A; TaMin_C: -55°C; TaMax_C: 150°C; SizeAreaWB_mm2: 14; SizeArea_mm2: 7.5; SizeX_mm: 2.5; SizeY_mm: 3; SizeZ_mm: 1.1; U/M: EA; AEC Category: Q101; AEC Qualified: N
Q8-Q10 Q12 Q14 Q15 = CMP-0000947-2: MOSFET, N-CH, 100 V, 0.17 A, SOT-23; Manufacturer: Fairchild Semiconductor; Alternate Manufacturer: None; U/M: EA; ChType: N; Value: 100V; Value1: 1; Rdson45_ohm: 10; Value2: 1.8 nC; QgTyp_nC: 1.8; Vgs_V: 20V; IdsMax_A: 1.7dA; AEC Category: Q101; SizeArea_mm2: 7.5; SizeAreaWB_mm2: 14; SizeX_mm: 2.5; SizeY_mm: 3; SizeZ_mm: 1.1
Q11 Q16 = CMP-0000962-2: MOSFET, N-CH, 100 V, 10 A, DQJ0008A (VSONP-8); Manufacturer: Texas Instruments; Alternate Manufacturer: None; U/M: EA; ChType: N; Value: 100V; Value2: 17 nC; QgTyp_nC: 17; Vgs_V: 20V; IdsMax_A: 10A; SizeAreaWB_mm2: 55.2; SizeArea_mm2: 29.4; SizeX_mm: 6; SizeY_mm: 4.9; SizeZ_mm: 1.1; AEC Category: Q101
R33 = CMP-0022204-4: RES, 20.0 k, 1%, 0.1 W, AEC-Q200 Grade 0, 0603; PartNumber: CRCW060320K0FKEA; Manufacturer: Vishay-Dale; Value: 20.0k; Res_ohm: 20k; Value_Code: 20k0; Power_W: 100mW; Value2: 0.1W; VDC_V: 75V; TempCo: 100 ppm/C; SizeArea_mm2: 1.28; SizeX_mm: 1.6; SizeY_mm: 0.8; SizeZ_mm: 1; EIA_Code: E96; AEC Category: Q200; AEC Qualified: Y; AEC Grade: 0
R34 R69 = CMP-0021998-4: RES, 10.0 k, 1%, 0.1 W, AEC-Q200 Grade 0, 0603; PartNumber: CRCW060310K0FKEA; Manufacturer: Vishay-Dale; Value: 10.0k; Res_ohm: 10k; Value_Code: 10k0; Power_W: 100mW; Value2: 0.1W; VDC_V: 75V; TempCo: 100 ppm/C; SizeArea_mm2: 1.28; SizeX_mm: 1.6; SizeY_mm: 0.8; SizeZ_mm: 1; EIA_Code: E96; AEC Category: Q200; AEC Qualified: Y; AEC Grade: 0
R35 R62 = CMP-0022254-4: RES, 27.4 k, 1%, 0.1 W, AEC-Q200 Grade 0, 0603; PartNumber: CRCW060327K4FKEA; Manufacturer: Vishay-Dale; Value: 27.4k; Value_Code: 27k4; Power_W: 100mW; Value2: 0.1W; VDC_V: 75V; TempCo: 100 ppm/C; EIA_Code: E96; SizeArea_mm2: 1.28; SizeX_mm: 1.6; SizeY_mm: 0.8; SizeZ_mm: 1; AEC Category: Q200; AEC Qualified: Y; AEC Grade: 0
R36 R38 R58 R59 = CMP-0023050-5: RES, 35.7 k, 1%, 0.1 W, 0603; Manufacturer: Yageo; CompType: Resistor; Value: 35.7k; Value_Code: 35k7; Power_W: 100mW; Value2: 0.1W; VDC_V: 75V; TempCo: 100 ppm/C; EIA_Code: E96; AEC Category: Q200; AEC Qualified: N; SizeArea_mm2: 1.28; SizeX_mm: 1.6; SizeY_mm: 0.8; SizeZ_mm: 1; SizeAreaWB_mm2: 4.68
R37 R40 R41 R43 R61 R66 R76 = CMP-0021990-4: RES, 100 k, 1%, 0.1 W, AEC-Q200 Grade 0, 0603; PartNumber: CRCW0603100KFKEA; Manufacturer: Vishay-Dale; Value: 100k; Power_W: 100mW; Value2: 0.1W; VDC_V: 75V; TempCo: 100 ppm/C; SizeArea_mm2: 1.28; SizeX_mm: 1.6; SizeY_mm: 0.8; SizeZ_mm: 1; EIA_Code: E96; AEC Category: Q200; AEC Qualified: Y; AEC Grade: 0
R39 R65 = CMP-0022040-4: RES, 137 k, 1%, 0.1 W, AEC-Q200 Grade 0, 0603; PartNumber: CRCW0603137KFKEA; Manufacturer: Vishay-Dale; Value: 137k; Power_W: 100mW; Value2: 0.1W; VDC_V: 75V; TempCo: 100 ppm/C; SizeArea_mm2: 1.28; SizeX_mm: 1.6; SizeY_mm: 0.8; SizeZ_mm: 1; EIA_Code: E96; AEC Category: Q200; AEC Qualified: Y; AEC Grade: 0
R42 = CMP-0022532-4: RES, 60.4 k, 1%, 0.1 W, AEC-Q200 Grade 0, 0603; Manufacturer: Vishay-Dale; CompType: Resistor; Value: 60.4k; Value_Code: 60k4; Power_W: 100mW; Value2: 0.1W; VDC_V: 75V; TempCo: 100 ppm/C; EIA_Code: E96; AEC Category: Q200; AEC Qualified: Y; AEC Grade: 0; SizeArea_mm2: 1.28; SizeX_mm: 1.6; SizeY_mm: 0.8; SizeZ_mm: 1
R44 R45 = CMP-0022133-4: RES, 1.78 k, 1%, 0.1 W, AEC-Q200 Grade 0, 0603; PartNumber: CRCW06031K78FKEA; Manufacturer: Vishay-Dale; Value: 1.78k; Value_Code: 1k78; Power_W: 100mW; Value2: 0.1W; VDC_V: 75V; TempCo: 100 ppm/C; SizeArea_mm2: 1.28; SizeX_mm: 1.6; SizeY_mm: 0.8; SizeZ_mm: 1; EIA_Code: E96; AEC Category: Q200; AEC Qualified: Y; AEC Grade: 0
R47 R71 = CMP-0021376-3: RES, 63.4, 1%, 0.125 W, AEC-Q200 Grade 0, 0805; PartNumber: CRCW080563R4FKEA; Manufacturer: Vishay-Dale; Value: 63.4; Value_Code: 63R4; Power_W: 125mW; VDC_V: 150V; TempCo: 100 ppm/C; EIA_Code: E96; AEC Category: Q200; AEC Grade: 0; AEC Qualified: Y; SizeArea_mm2: 2.5; SizeX_mm: 2; SizeY_mm: 1.25; SizeZ_mm: 1.45
R48 R72 = CMP-0020959-3: RES, 1.21 k, 1%, 0.125 W, AEC-Q200 Grade 0, 0805; Manufacturer: Vishay-Dale; CompType: Resistor; Value: 1.21k; Value_Code: 1k21; Power_W: 125mW; VDC_V: 150V; TempCo: 100 ppm/C; EIA_Code: E96; AEC Category: Q200; AEC Grade: 0; AEC Qualified: Y; SizeArea_mm2: 2.5; SizeX_mm: 2; SizeY_mm: 1.25; SizeZ_mm: 1.45
R49 R52 = CMP-0022426-4: RES, 44.2 k, 1%, 0.1 W, AEC-Q200 Grade 0, 0603; PartNumber: CRCW060344K2FKEA; Manufacturer: Vishay-Dale; Value: 44.2k; Value_Code: 44k2; Power_W: 100mW; Value2: 0.1W; VDC_V: 75V; TempCo: 100 ppm/C; EIA_Code: E96; AEC Category: Q200; AEC Grade: 0; AEC Qualified: Y; SizeArea_mm2: 1.28; SizeX_mm: 1.6; SizeY_mm: 0.8; SizeZ_mm: 1
R50 R70 = CMP-0020476-3: RES, 1.3 k, 5%, 0.125 W, AEC-Q200 Grade 0, 0805; PartNumber: CRCW08051K30JNEA; Manufacturer: Vishay-Dale; Value: 1.3k; Value_Code: 1k30; Power_W: 125mW; VDC_V: 150V; TempCo: 200 ppm/C; EIA_Code: E24; AEC Category: Q200; AEC Qualified: Y; AEC Grade: 0; SizeArea_mm2: 2.5; SizeX_mm: 2; SizeY_mm: 1.25; SizeZ_mm: 1.45
R53 R55 R57 = CMP-0021998-4: RES, 10.0 k, 1%, 0.1 W, AEC-Q200 Grade 0, 0603; PartNumber: CRCW060310K0FKEA; Manufacturer: Vishay-Dale; Value: 10.0k; Res_ohm: 10k; Value_Code: 10k0; Power_W: 100mW; Value2: 0.1W; VDC_V: 75V; TempCo: 100 ppm/C; EIA_Code: E96; AEC Category: Q200; AEC Grade: 0; AEC Qualified: Y; SizeArea_mm2: 1.28; SizeX_mm: 1.6; SizeY_mm: 0.8; SizeZ_mm: 1
R54 R75 = CMP-0022447-4: RES, 49.9 k, 1%, 0.1 W, AEC-Q200 Grade 0, 0603; PartNumber: CRCW060349K9FKEA; Manufacturer: Vishay-Dale; Value: 49.9k; Value_Code: 49k9; Power_W: 100mW; Value2: 0.1W; VDC_V: 75V; TempCo: 100 ppm/C; EIA_Code: E96; AEC Category: Q200; AEC Qualified: Y; AEC Grade: 0; SizeArea_mm2: 1.28; SizeX_mm: 1.6; SizeY_mm: 0.8; SizeZ_mm: 1
R56 = CMP-0022109-5: RES, 1.00 k, 1%, 0.1 W, AEC-Q200 Grade 0, 0603; PartNumber: CRCW06031K00FKEA; Manufacturer: Vishay-Dale; Value: 1.00k; Res_ohm: 1k; Value_Code: 1k00; Power_W: 100mW; Value2: 0.1W; VDC_V: 75V; TempCo: 100 ppm/C; SizeArea_mm2: 1.28; SizeX_mm: 1.6; SizeY_mm: 0.8; SizeZ_mm: 1; EIA_Code: E96; AEC Category: Q200; AEC Qualified: Y; AEC Grade: 0
R60 = CMP-0021998-4: RES, 10.0 k, 1%, 0.1 W, AEC-Q200 Grade 0, 0603; Manufacturer: Vishay-Dale; Value: 10.0k; Res_ohm: 10k; Value_Code: 10k0; Power_W: 100mW; Value2: 0.1W; VDC_V: 75V; TempCo: 100 ppm/C; SizeArea_mm2: 1.28; SizeX_mm: 1.6; SizeY_mm: 0.8; SizeZ_mm: 1; EIA_Code: E96; AEC Category: Q200; AEC Qualified: Y; AEC Grade: 0
R67 = CMP-0022532-4: RES, 60.4 k, 1%, 0.1 W, AEC-Q200 Grade 0, 0603; Manufacturer: Vishay-Dale; Value: 60.4k; Value_Code: 60k4; Power_W: 100mW; Value2: 0.1W; VDC_V: 75V; TempCo: 100 ppm/C; EIA_Code: E96; AEC Category: Q200; AEC Qualified: Y; AEC Grade: 0; SizeArea_mm2: 1.28; SizeX_mm: 1.6; SizeY_mm: 0.8; SizeZ_mm: 1
R74 = CMP-0022204-4: RES, 20.0 k, 1%, 0.1 W, AEC-Q200 Grade 0, 0603; PartNumber: CRCW060320K0FKEA; Manufacturer: Vishay-Dale; Value: 20.0k; Res_ohm: 20k; Value_Code: 20k0; Power_W: 100mW; Value2: 0.1W; VDC_V: 75V; TempCo: 100 ppm/C; EIA_Code: E96; SizeArea_mm2: 1.28; SizeX_mm: 1.6; SizeY_mm: 0.8; SizeZ_mm: 1; AEC Category: Q200; AEC Qualified: Y; AEC Grade: 0
R77 = CMP-0022110-4: RES, 1.02 k, 1%, 0.1 W, AEC-Q200 Grade 0, 0603; PartNumber: CRCW06031K02FKEA; Manufacturer: Vishay-Dale; Value: 1.02k; Value_Code: 1k02; Power_W: 100mW; Value2: 0.1W; VDC_V: 75V; TempCo: 100 ppm/C; SizeArea_mm2: 1.28; SizeX_mm: 1.6; SizeY_mm: 0.8; SizeZ_mm: 1; EIA_Code: E96; AEC Category: Q200; AEC Qualified: Y; AEC Grade: 0
R100 R101 = CMP-0022324-4: RES, 30.1 k, 1%, 0.1 W, AEC-Q200 Grade 0, 0603; PartNumber: CRCW060330K1FKEA; Manufacturer: Vishay-Dale; Value: 30.1k; Value_Code: 30k1; Power_W: 100mW; Value2: 0.1W; VDC_V: 75V; TempCo: 100 ppm/C; SizeArea_mm2: 1.28; SizeX_mm: 1.6; SizeY_mm: 0.8; SizeZ_mm: 1; EIA_Code: E96; AEC Category: Q200; AEC Qualified: Y; AEC Grade: 0
U1 U5 = CMP-0013755-3: IEEE 802.3bt PoE High-Power PD Interface with Automatic MPS & Autoclass, RGW0020B (VQFN-20); Alternate PartNumber: TPS2372-3RGWT; Manufacturer: Texas Instruments; SizeArea_mm2: 25; SizeAreaWB_mm2: 49; SizeX_mm: 5; SizeZ_mm: 1; CompType: IC; AEC Category: Q200; AEC Qualified: N
U2-U4 U10 U11 = CMP-0006164-3: Optocoupler, 3.75 kV, 80-160% CTR, SMT; Manufacturer: Fairchild Semiconductor; CTR (Min): 80%; CTR (Max): 160%; Voltage_Isolation_Vrms: 3.75kV; SizeAreaWB_mm2: 4; SizeArea_mm2: 1
U6 = CMP-0032355-1: Low Quiescent Current, Programmable-Delay Supervisory Circuit, 1 Supply Monitored, -40 to 125 degC, 6-pin SOT-23 (DBV), Green (RoHS & no Sb/Br); Manufacturer: Texas Instruments; # of Supplies Monitored: 1; Iq(Typ)(uA): 2.4; Output Driver Type / Reset Output: Active-low, Open-drain; Rating: Catalog; SubFamily: Supervisor and Reset IC; Threshold Voltage 1 (typ)(Typ)(V): Adjustable; VCC(Max)(V): 6.5; VCC(Min)(V): 1.7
